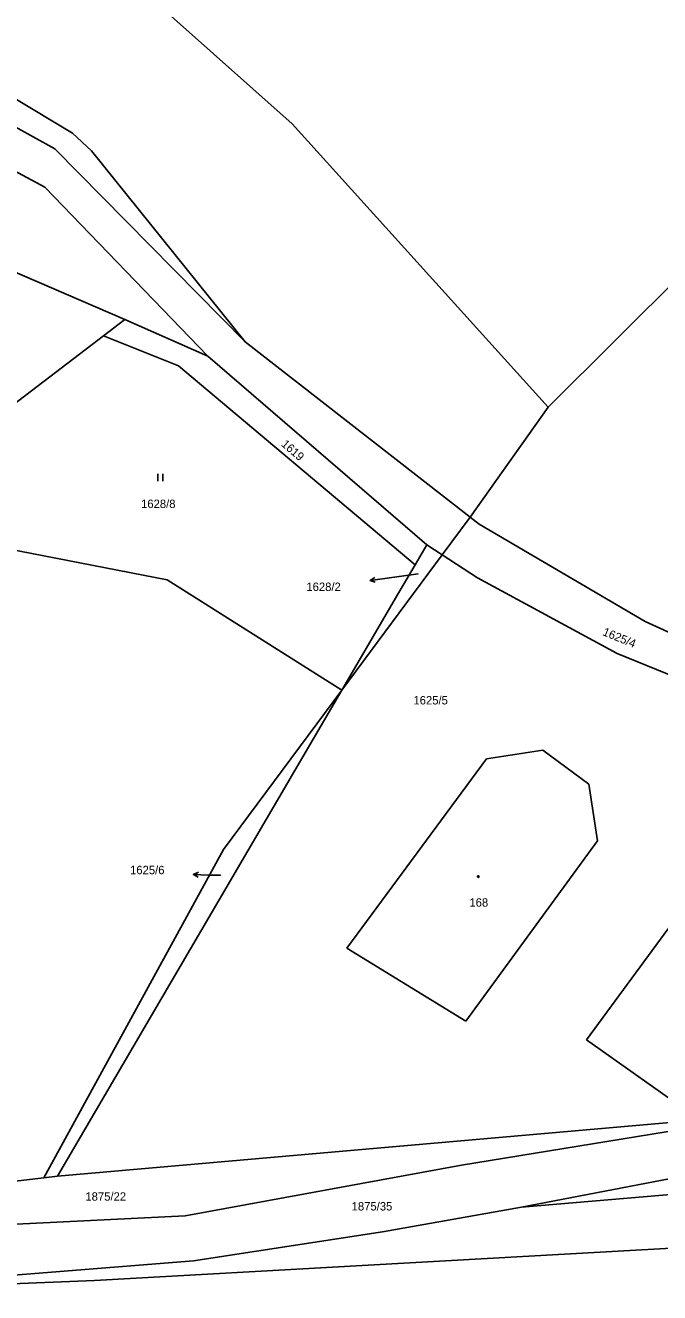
# Model space of a CAD drawing. Extents: x -747792 to -745414, y -1093712 to -1091463.
# Drawn here: x -747210.3 to -747146.2, y -1092151.4 to -1092023.4 of the extents above; entities that cross this region are included whole.
import ezdxf

# ---------------------------------------------------------------- set-up
doc = ezdxf.new("R2010")
doc.units = 0
for name, color, linetype in [('Budovy', 7, 'Continuous'), ('Doplňkové značky', 7, 'Continuous'), ('Koleje_dopravní prvky', 7, 'Continuous'), ('Ploty_opěrné zdi', 7, 'Continuous'), ('Stromy_porost', 7, 'Continuous')]:
    doc.layers.add(name, color=color, linetype=linetype)

msp = doc.modelspace()

# ---------------------------------------------------------------- linework, layer by layer
at = {"layer": 'Budovy'}
for points in [[(-747196.88, -1092068.73), (-747196.88, -1092069.48)], [(-747196.38, -1092069.48), (-747196.38, -1092068.73)]]:
    msp.add_lwpolyline(points, dxfattribs=at)
at = {"layer": 'Doplňkové značky'}
for points in [[(-747170.59, -1092078.84), (-747173.97, -1092079.3)], [(-747174.93, -1092079.68), (-747175.46, -1092079.5), (-747174.99, -1092079.19)], [(-747175.46, -1092079.5), (-747173.97, -1092079.3)], [(-747192.81, -1092109.47), (-747193.3, -1092109.21), (-747192.79, -1092108.97)], [(-747193.3, -1092109.21), (-747191.8, -1092109.25)], [(-747190.56, -1092109.28), (-747191.8, -1092109.25)]]:
    msp.add_lwpolyline(points, dxfattribs=at)
at = {"layer": 'Ploty_opěrné zdi'}
msp.add_lwpolyline([(-747164.54, -1092109.32), (-747164.49, -1092109.33), (-747164.47, -1092109.38), (-747164.46, -1092109.41), (-747164.47, -1092109.46), (-747164.51, -1092109.49), (-747164.54, -1092109.49), (-747164.58, -1092109.48), (-747164.61, -1092109.45), (-747164.62, -1092109.41), (-747164.61, -1092109.36), (-747164.58, -1092109.33)], close=True, dxfattribs=at)
at = {"layer": 'Stromy_porost'}
for points in [[(-747203.47, -1092015.38), (-747183.31, -1092033.37)], [(-747251.1, -1092016.73), (-747208.29, -1092039.75)], [(-747207.3, -1092035.89), (-747219.39, -1092029.19)], [(-747205.49, -1092034.31), (-747211.48, -1092030.71)], [(-747183.31, -1092033.37), (-747157.47, -1092061.98)], [(-747203.58, -1092036.09), (-747205.49, -1092034.31)], [(-747188.08, -1092055.4), (-747207.3, -1092035.89)], [(-747203.58, -1092036.09), (-747188.08, -1092055.4)], [(-747191.85, -1092056.84), (-747208.29, -1092039.75)], [(-747200.22, -1092053.14), (-747215.07, -1092046.72)], [(-747157.47, -1092061.98), (-747143.72, -1092048.29)], [(-747200.22, -1092053.14), (-747202.36, -1092054.78)], [(-747191.85, -1092056.84), (-747200.22, -1092053.14)], [(-747202.36, -1092054.78), (-747227.92, -1092074.29)], [(-747194.8, -1092057.8), (-747202.36, -1092054.78)], [(-747165.36, -1092073.11), (-747188.08, -1092055.4)], [(-747169.72, -1092075.88), (-747191.85, -1092056.84)], [(-747170.91, -1092077.91), (-747194.8, -1092057.8)], [(-747157.47, -1092061.98), (-747165.36, -1092073.11)], [(-747165.36, -1092073.11), (-747168.17, -1092076.9)], [(-747164.46, -1092073.81), (-747165.36, -1092073.11)], [(-747147.69, -1092083.64), (-747164.46, -1092073.81)], [(-747195.96, -1092079.44), (-747222.08, -1092074.35)], [(-747169.72, -1092075.88), (-747170.91, -1092077.91)], [(-747169.72, -1092075.88), (-747168.17, -1092076.9)], [(-747168.17, -1092076.9), (-747178.3, -1092090.57)], [(-747168.17, -1092076.9), (-747164.61, -1092079.24)], [(-747170.91, -1092077.91), (-747172.54, -1092080.72)], [(-747178.3, -1092090.57), (-747195.96, -1092079.44)], [(-747164.61, -1092079.24), (-747150.51, -1092086.89)], [(-747172.54, -1092080.72), (-747178.3, -1092090.57)], [(-747128.84, -1092092.24), (-747147.69, -1092083.64)], [(-747150.51, -1092086.89), (-747130.84, -1092094.88)], [(-747178.3, -1092090.57), (-747207.03, -1092139.68)], [(-747190.27, -1092106.67), (-747178.3, -1092090.57)], [(-747153.61, -1092125.9), (-747130.84, -1092094.88)], [(-747158.02, -1092096.65), (-747163.69, -1092097.53)], [(-747153.37, -1092100.07), (-747158.02, -1092096.65)], [(-747163.69, -1092097.53), (-747177.82, -1092116.64)], [(-747152.5, -1092105.8), (-747153.37, -1092100.07)], [(-747165.78, -1092124.03), (-747152.5, -1092105.8)], [(-747208.4, -1092139.84), (-747190.27, -1092106.67)], [(-747177.82, -1092116.64), (-747165.78, -1092124.03)], [(-747144.76, -1092132.15), (-747153.61, -1092125.9)], [(-747207.03, -1092139.68), (-747140.56, -1092133.84)], [(-747132.35, -1092133.04), (-747166.22, -1092138.57)], [(-747160.16, -1092142.79), (-747120.04, -1092135.1)], [(-747166.22, -1092138.57), (-747194.11, -1092143.68)], [(-747208.4, -1092139.84), (-747224.76, -1092141.77)], [(-747207.03, -1092139.68), (-747208.4, -1092139.84)], [(-747142.32, -1092141.28), (-747160.16, -1092142.79)], [(-747160.16, -1092142.79), (-747174.2, -1092145.31)], [(-747194.11, -1092143.68), (-747216.67, -1092144.8)], [(-747120.38, -1092145.57), (-747203.28, -1092150.22)], [(-747174.2, -1092145.31), (-747193.27, -1092148.22)], [(-747193.27, -1092148.22), (-747233.36, -1092151.44)], [(-747203.28, -1092150.22), (-747233.36, -1092151.44)]]:
    msp.add_lwpolyline(points, dxfattribs=at)

# ---------------------------------------------------------------- texts
at = {"layer": 'Doplňkové značky'}
for s, p in [('1628/2', (-747181.89, -1092080.56)), ('1625/6', (-747199.69, -1092109.17))]:
    msp.add_text(s, height=0.85, dxfattribs=at).set_placement(p)
at = {"layer": 'Koleje_dopravní prvky'}
for s, rotation, p in [('1619', 319.2521, (-747184.49, -1092065.83)), ('1625/4', 337.644, (-747152.05, -1092085))]:
    msp.add_text(s, height=0.85, rotation=rotation, dxfattribs=at).set_placement(p)
for s, height, p in [('1628/8', 0.85, (-747198.58, -1092072.18)), ('1628/2', 0.05, (-747170.71, -1092078.84)), ('1625/5', 0.85, (-747171.08, -1092092.02)), ('1625/6', 0.05, (-747190.67, -1092109.28)), ('168', 0.85, (-747165.43, -1092112.45)), ('1875/22', 0.85, (-747204.2, -1092142.15)), ('1875/35', 0.85, (-747177.32, -1092143.14))]:
    msp.add_text(s, height=height, dxfattribs=at).set_placement(p)

doc.saveas('drawing.dxf')
